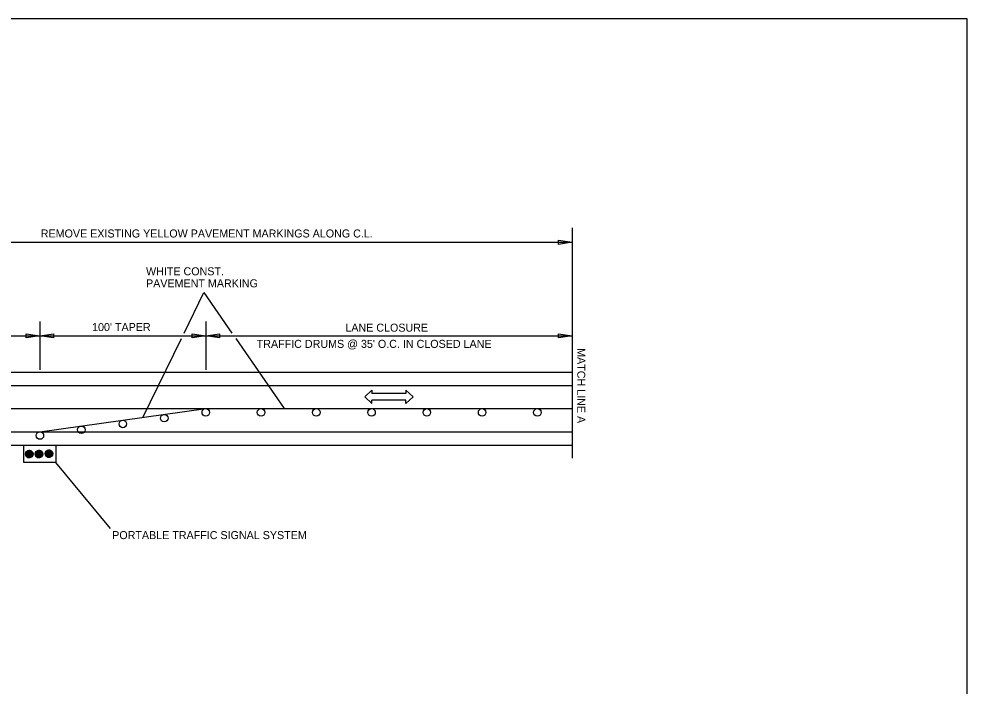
# Model space of a CAD drawing. Extents: x 1806907 to 1812607, y 675071 to 676228.
# Drawn here: x 1809871 to 1810582, y 675571 to 676070 of the extents above; entities that cross this region are included whole.
import ezdxf

# ---------------------------------------------------------------- set-up
doc = ezdxf.new("R2010")
doc.units = 0
for name, color, linetype in [('Default', 7, 'Continuous'), ('DSN_DRFT_Named-Boundary', 7, 'Continuous'), ('R_MOT', 7, 'Continuous')]:
    doc.layers.add(name, color=color, linetype=linetype)

msp = doc.modelspace()

# ---------------------------------------------------------------- linework, layer by layer
at = {"layer": 'Default'}
for p, q in [((1810285.86, 675913.79), (1810285.86, 675741.43)), ((1809762.67, 675903.01), (1810285.86, 675903.01)), ((1810275.55, 675901.46), (1810275.55, 675904.56)), ((1810275.55, 675904.56), (1810285.86, 675903.01)), ((1810285.86, 675903.01), (1810275.55, 675901.46)), ((1809886.96, 675843.73), (1809886.96, 675807.57)), ((1810011.25, 675843.73), (1810011.25, 675807.57)), ((1809762.67, 675832.95), (1809886.96, 675832.95)), ((1809876.65, 675831.4), (1809876.65, 675834.49)), ((1809876.65, 675834.49), (1809886.96, 675832.95)), ((1809886.96, 675832.95), (1809876.65, 675831.4)), ((1809886.96, 675832.95), (1809897.26, 675834.49)), ((1809886.96, 675832.95), (1810011.25, 675832.95)), ((1809897.26, 675831.4), (1809886.96, 675832.95)), ((1809897.26, 675834.49), (1809897.26, 675831.4)), ((1810000.94, 675831.4), (1810000.94, 675834.49)), ((1810000.94, 675834.49), (1810011.25, 675832.95)), ((1810011.25, 675832.95), (1810000.94, 675831.4)), ((1810011.25, 675832.95), (1810021.55, 675834.49)), ((1810021.55, 675831.4), (1810011.25, 675832.95)), ((1810011.25, 675832.95), (1810285.86, 675832.95)), ((1810021.55, 675834.49), (1810021.55, 675831.4)), ((1810275.55, 675831.4), (1810275.55, 675834.49)), ((1810275.55, 675834.49), (1810285.86, 675832.95)), ((1810285.86, 675832.95), (1810275.55, 675831.4)), ((1809227.51, 675805.87), (1810285.86, 675805.87)), ((1809776.27, 675795.87), (1810285.86, 675795.87)), ((1809761.42, 675778.48), (1810285.86, 675778.48)), ((1809886.96, 675761.1), (1810011.25, 675778.48)), ((1809776.27, 675761.1), (1810061.57, 675761.1)), ((1810061.57, 675761.1), (1810285.86, 675761.1)), ((1809227.51, 675751.1), (1810285.86, 675751.1)), ((1809876.14, 675744.94), (1809879.5, 675741.58)), ((1809876.17, 675745.09), (1809879.64, 675741.62)), ((1809876.21, 675745.23), (1809879.78, 675741.65)), ((1809876.25, 675745.36), (1809879.91, 675741.7)), ((1809876.35, 675745.61), (1809880.17, 675741.8)), ((1809876.41, 675745.73), (1809880.28, 675741.86)), ((1809876.47, 675745.85), (1809880.4, 675741.92)), ((1809876.54, 675745.96), (1809880.51, 675741.99)), ((1809876.61, 675746.06), (1809880.61, 675742.06)), ((1809876.68, 675746.16), (1809880.72, 675742.13)), ((1809876.76, 675746.26), (1809880.81, 675742.21)), ((1809876.85, 675746.36), (1809880.91, 675742.29)), ((1809876.93, 675746.45), (1809881, 675742.38)), ((1809877.02, 675746.53), (1809881.08, 675742.47)), ((1809877.12, 675746.62), (1809881.17, 675742.57)), ((1809877.22, 675746.69), (1809881.25, 675742.66)), ((1809877.32, 675746.77), (1809881.32, 675742.77)), ((1809877.42, 675746.84), (1809881.39, 675742.87)), ((1809877.53, 675746.91), (1809881.46, 675742.98)), ((1809877.65, 675746.97), (1809881.52, 675743.1)), ((1809877.77, 675747.02), (1809881.58, 675743.22)), ((1809877.89, 675747.08), (1809881.63, 675743.34)), ((1809878.02, 675747.13), (1809881.68, 675743.47)), ((1809878.15, 675747.17), (1809881.72, 675743.6)), ((1809878.29, 675747.21), (1809881.76, 675743.74)), ((1809878.44, 675747.24), (1809881.79, 675743.89)), ((1809878.59, 675747.26), (1809881.81, 675744.04)), ((1809878.75, 675747.28), (1809881.83, 675744.2)), ((1809878.92, 675747.28), (1809881.84, 675744.37)), ((1809879.1, 675747.28), (1809881.83, 675744.55)), ((1809879.3, 675747.26), (1809881.82, 675744.75)), ((1809879.51, 675747.23), (1809881.78, 675744.95)), ((1809879.74, 675747.18), (1809881.73, 675745.19)), ((1809880, 675747.09), (1809881.64, 675745.45)), ((1809880.33, 675746.94), (1809881.49, 675745.78)), ((1809883.42, 675745.01), (1809886.83, 675741.6)), ((1809883.45, 675745.15), (1809886.97, 675741.63)), ((1809883.49, 675745.29), (1809887.11, 675741.67)), ((1809883.54, 675745.42), (1809887.24, 675741.72)), ((1809883.59, 675745.55), (1809887.37, 675741.77)), ((1809883.65, 675745.67), (1809887.49, 675741.82)), ((1809883.71, 675745.78), (1809887.61, 675741.88)), ((1809883.77, 675745.9), (1809887.72, 675741.95)), ((1809883.84, 675746), (1809887.83, 675742.02)), ((1809883.91, 675746.11), (1809887.93, 675742.09)), ((1809883.99, 675746.21), (1809888.03, 675742.17)), ((1809884.07, 675746.3), (1809888.13, 675742.25)), ((1809884.15, 675746.4), (1809888.22, 675742.33)), ((1809884.24, 675746.49), (1809888.31, 675742.42)), ((1809884.33, 675746.57), (1809888.39, 675742.51)), ((1809884.43, 675746.65), (1809888.47, 675742.61)), ((1809884.53, 675746.73), (1809888.55, 675742.71)), ((1809884.63, 675746.8), (1809888.62, 675742.81)), ((1809884.74, 675746.87), (1809888.69, 675742.92)), ((1809884.85, 675746.93), (1809888.75, 675743.03)), ((1809884.97, 675746.99), (1809888.81, 675743.15)), ((1809885.09, 675747.05), (1809888.87, 675743.27)), ((1809885.22, 675747.1), (1809888.92, 675743.4)), ((1809885.35, 675747.15), (1809888.97, 675743.53)), ((1809885.49, 675747.19), (1809889.01, 675743.66)), ((1809885.63, 675747.22), (1809889.04, 675743.81)), ((1809885.78, 675747.25), (1809889.07, 675743.96)), ((1809885.93, 675747.27), (1809889.09, 675744.11)), ((1809886.1, 675747.28), (1809889.1, 675744.28)), ((1809886.27, 675747.28), (1809889.11, 675744.45)), ((1809886.46, 675747.27), (1809889.1, 675744.64)), ((1809886.66, 675747.25), (1809889.07, 675744.84)), ((1809886.88, 675747.21), (1809889.03, 675745.05)), ((1809887.12, 675747.14), (1809888.96, 675745.3)), ((1809887.41, 675747.03), (1809888.85, 675745.59)), ((1809887.8, 675746.82), (1809888.64, 675745.97)), ((1809890.86, 675744.97), (1809894.01, 675741.81)), ((1809890.88, 675745.12), (1809894.17, 675741.83)), ((1809890.9, 675745.27), (1809894.32, 675741.86)), ((1809890.94, 675745.42), (1809894.46, 675741.9)), ((1809890.98, 675745.55), (1809894.6, 675741.94)), ((1809891.02, 675745.68), (1809894.73, 675741.98)), ((1809891.08, 675745.81), (1809894.85, 675742.03)), ((1809891.13, 675745.93), (1809894.97, 675742.09)), ((1809891.19, 675746.05), (1809895.09, 675742.15)), ((1809891.26, 675746.16), (1809895.2, 675742.21)), ((1809891.32, 675746.27), (1809895.31, 675742.28)), ((1809891.4, 675746.37), (1809895.41, 675742.35)), ((1809891.47, 675746.47), (1809895.51, 675742.43)), ((1809891.55, 675746.57), (1809895.61, 675742.51)), ((1809891.64, 675746.66), (1809895.7, 675742.6)), ((1809891.73, 675746.75), (1809895.79, 675742.68)), ((1809891.82, 675746.83), (1809895.88, 675742.78)), ((1809891.92, 675746.91), (1809895.96, 675742.87)), ((1809892.02, 675746.99), (1809896.03, 675742.97)), ((1809892.12, 675747.06), (1809896.11, 675743.08)), ((1809892.23, 675747.13), (1809896.18, 675743.18)), ((1809892.34, 675747.2), (1809896.24, 675743.3)), ((1809892.46, 675747.26), (1809896.3, 675743.41)), ((1809892.58, 675747.31), (1809896.36, 675743.53)), ((1809892.7, 675747.36), (1809896.41, 675743.66)), ((1809892.83, 675747.41), (1809896.45, 675743.79)), ((1809892.97, 675747.45), (1809896.49, 675743.93)), ((1809893.11, 675747.48), (1809896.53, 675744.07)), ((1809893.26, 675747.51), (1809896.55, 675744.22)), ((1809893.42, 675747.53), (1809896.58, 675744.38)), ((1809893.58, 675747.54), (1809896.59, 675744.54)), ((1809893.76, 675747.55), (1809896.59, 675744.71)), ((1809893.94, 675747.54), (1809896.58, 675744.9)), ((1809894.14, 675747.52), (1809896.56, 675745.1)), ((1809894.36, 675747.47), (1809896.52, 675745.32)), ((1809894.6, 675747.41), (1809896.45, 675745.56)), ((1809894.89, 675747.29), (1809896.34, 675745.85)), ((1809895.28, 675747.08), (1809896.13, 675746.24)), ((1809876.09, 675744.63), (1809879.18, 675741.54)), ((1809876.09, 675744.46), (1809879.02, 675741.53)), ((1809876.09, 675744.29), (1809878.84, 675741.54)), ((1809876.1, 675744.09), (1809878.65, 675741.55)), ((1809876.11, 675744.79), (1809879.34, 675741.56)), ((1809876.13, 675743.89), (1809878.44, 675741.58)), ((1809876.19, 675743.66), (1809878.21, 675741.63)), ((1809876.27, 675743.4), (1809877.95, 675741.72)), ((1809876.41, 675743.08), (1809877.63, 675741.86)), ((1809876.8, 675742.52), (1809877.07, 675742.24)), ((1809883.36, 675744.54), (1809886.36, 675741.54)), ((1809883.36, 675744.37), (1809886.19, 675741.53)), ((1809883.36, 675744.18), (1809886, 675741.54)), ((1809883.37, 675744.7), (1809886.53, 675741.55)), ((1809883.39, 675744.86), (1809886.68, 675741.57)), ((1809883.39, 675743.98), (1809885.8, 675741.57)), ((1809883.43, 675743.76), (1809885.58, 675741.61)), ((1809883.5, 675743.52), (1809885.34, 675741.68)), ((1809883.61, 675743.23), (1809885.05, 675741.79)), ((1809883.82, 675742.84), (1809884.66, 675742)), ((1809890.84, 675744.8), (1809893.85, 675741.8)), ((1809890.84, 675744.63), (1809893.67, 675741.8)), ((1809890.85, 675744.44), (1809893.49, 675741.81)), ((1809890.87, 675744.24), (1809893.29, 675741.83)), ((1809890.91, 675744.03), (1809893.07, 675741.87)), ((1809890.98, 675743.78), (1809892.82, 675741.94)), ((1809891.09, 675743.49), (1809892.54, 675742.05)), ((1809891.31, 675743.1), (1809892.15, 675742.26))]:
    msp.add_line(p, q, dxfattribs=at)
for points in [[(1809994.99, 675834.95), (1810009.85, 675865.31), (1810030.91, 675834.95)], [(1809964.12, 675771.89), (1809993.03, 675830.95)], [(1810033.68, 675830.95), (1810070.07, 675778.48)], [(1810011.25, 675778.48), (1810285.86, 675778.48)], [(1809939.89, 675688.78), (1809898.95, 675738.11)]]:
    msp.add_lwpolyline(points, dxfattribs=at)
msp.add_lwpolyline([(1809898.95, 675751.1), (1809898.95, 675738.11), (1809874.97, 675738.11), (1809874.97, 675751.1)], close=True, dxfattribs=at)
for centre, radius in [((1809980.17, 675771.32), 2.81), ((1810011.25, 675775.67), 2.81), ((1810052.66, 675775.67), 2.81), ((1810094.07, 675775.67), 2.81), ((1810135.49, 675775.67), 2.81), ((1810176.9, 675775.67), 2.81), ((1810218.31, 675775.67), 2.81), ((1810259.73, 675775.67), 2.81), ((1809949.1, 675766.98), 2.81), ((1809886.96, 675758.29), 2.81), ((1809918.03, 675762.63), 2.81), ((1809878.96, 675744.41), 2.87), ((1809886.23, 675744.41), 2.87), ((1809893.72, 675744.67), 2.87)]:
    msp.add_circle(centre, radius, dxfattribs=at)
at = {"layer": 'DSN_DRFT_Named-Boundary'}
msp.add_lwpolyline([(1808931.68, 675071.2), (1810581.68, 675071.2), (1810581.68, 676070.26), (1808931.68, 676070.26)], close=True, dxfattribs=at)
at = {"layer": 'R_MOT'}
for p, q in [((1810130.33, 675787.18), (1810135.81, 675792.18)), ((1810135.81, 675792.18), (1810135.81, 675789.68)), ((1810161.29, 675789.68), (1810135.81, 675789.68)), ((1810161.29, 675792.18), (1810166.78, 675787.18)), ((1810161.29, 675792.18), (1810161.29, 675789.68)), ((1810135.81, 675782.18), (1810130.33, 675787.18)), ((1810161.29, 675784.68), (1810135.81, 675784.68)), ((1810135.81, 675782.18), (1810135.81, 675784.68)), ((1810166.78, 675787.18), (1810161.29, 675782.18)), ((1810161.29, 675782.18), (1810161.29, 675784.68))]:
    msp.add_line(p, q, dxfattribs=at)

# ---------------------------------------------------------------- texts
at = {"layer": 'Default'}
for s, p in [('REMOVE EXISTING YELLOW PAVEMENT MARKINGS ALONG C.L.', (1809887.63, 675906.62)), ('WHITE CONST.', (1809966.5, 675878.3)), ('PAVEMENT MARKING', (1809966.5, 675869.3)), ("100' TAPER", (1809926.07, 675836.56)), ('LANE CLOSURE', (1810115.86, 675836.09)), ("TRAFFIC DRUMS @ 35' O.C. IN CLOSED LANE", (1810049.43, 675823.96)), ('PORTABLE TRAFFIC SIGNAL SYSTEM', (1809941.14, 675680.75))]:
    msp.add_text(s, height=6, dxfattribs=at).set_placement(p)
msp.add_text('MATCH LINE A', height=6, rotation=270, dxfattribs=at).set_placement((1810289.61, 675823.74))

doc.saveas('drawing.dxf')
